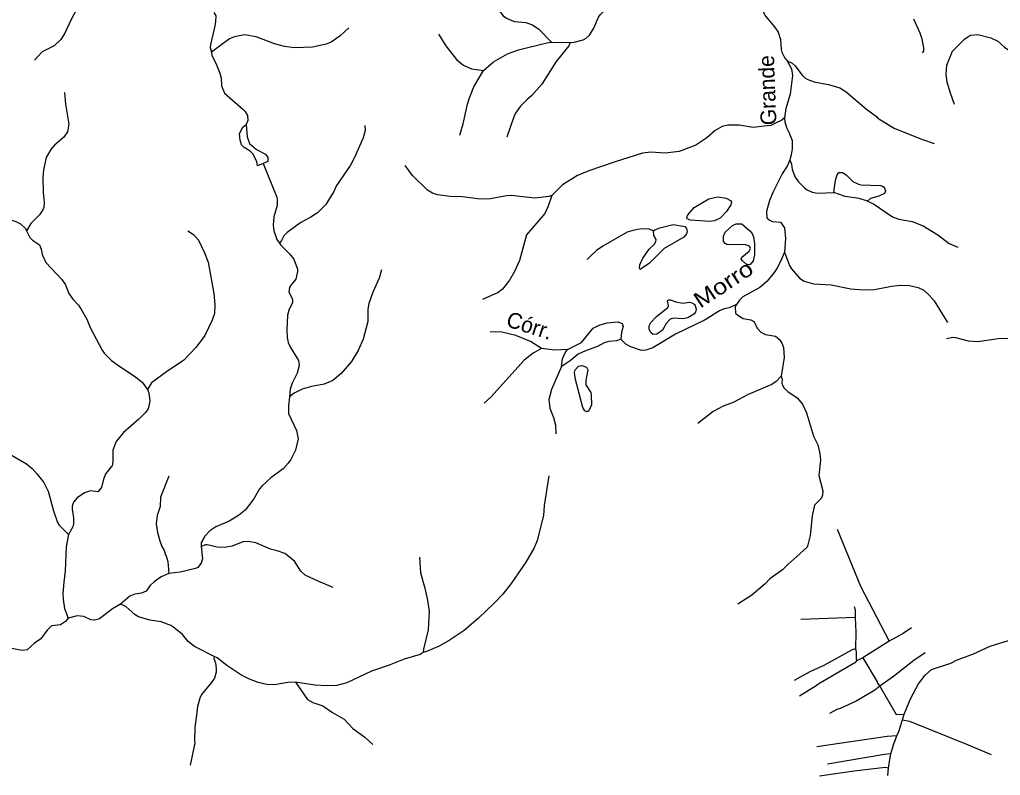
# Model space of a CAD drawing. Extents: x 346.5 to 372.4, y 7400.3 to 7428.2.
# Drawn here: x 356.096 to 361.094, y 7410.774 to 7414.626 of the extents above; entities that cross this region are included whole.
import ezdxf
from ezdxf.enums import TextEntityAlignment as Align

# ---------------------------------------------------------------- set-up
doc = ezdxf.new("R2010")
doc.units = 0
doc.header["$LTSCALE"] = 0.032
for name, color, linetype, lineweight in [('1', 7, 'Continuous', 25), ('2', 7, 'Continuous', 25), ('7', 7, 'Continuous', 25)]:
    doc.layers.add(name, color=color, linetype=linetype, lineweight=lineweight)
doc.layers.add('61', color=7, linetype='Continuous')

msp = doc.modelspace()

# ---------------------------------------------------------------- linework, layer by layer
at = {"layer": '1'}
msp.add_line((360.3537, 7411.5783), (360.0779, 7411.5678), dxfattribs=at)
for points in [[(360.262, 7412.0292), (360.3823, 7411.7384), (360.5278, 7411.4572)], [(360.3489, 7411.634), (360.3544, 7411.6172), (360.3537, 7411.5783)], [(360.3537, 7411.5783), (360.3576, 7411.5041), (360.3554, 7411.4183)], [(360.6406, 7411.5256), (360.5991, 7411.4977), (360.5278, 7411.4572), (360.3927, 7411.3731), (360.3618, 7411.3568)], [(360.3554, 7411.4183), (360.3398, 7411.414), (360.1951, 7411.3343), (360.1241, 7411.3008), (360.0429, 7411.257)], [(360.3554, 7411.4183), (360.36, 7411.4029), (360.3589, 7411.3696), (360.3618, 7411.3568)], [(360.3927, 7411.3731), (360.4668, 7411.2498), (360.4675, 7411.2439), (360.4807, 7411.2277)], [(360.7107, 7411.3981), (360.6541, 7411.3598), (360.5497, 7411.2769), (360.4807, 7411.2277)], [(360.3618, 7411.3568), (360.3533, 7411.3475), (360.1688, 7411.2411), (360.1664, 7411.2371), (360.1584, 7411.2347), (360.156, 7411.2307), (360.0699, 7411.1781)], [(360.4807, 7411.2277), (360.4549, 7411.2084), (360.3592, 7411.1526), (360.2748, 7411.1127), (360.2636, 7411.1111), (360.223, 7411.0889)], [(360.4807, 7411.2277), (360.5641, 7411.0848), (360.6036, 7411.0861)], [(360.5956, 7411.0574), (360.6318, 7411.0498), (360.9299, 7410.9302), (361.047, 7410.8793)], [(360.5668, 7410.9754), (360.517, 7410.9717), (360.1592, 7410.9191)], [(360.5359, 7410.8828), (360.5043, 7410.88), (360.2134, 7410.8314)], [(360.5245, 7410.8109), (360.5067, 7410.8143), (360.3497, 7410.7956), (360.172, 7410.7701)]]:
    msp.add_lwpolyline(points, dxfattribs=at)
at = {"layer": '2'}
for points in [[(357.2516, 7414.0922), (357.2559, 7414.0287), (357.2675, 7413.9947), (357.3039, 7413.9643), (357.3487, 7413.9397), (357.361, 7413.9232), (357.3617, 7413.9032), (357.3384, 7413.8931), (357.3092, 7413.8804), (357.3048, 7413.9011), (357.2862, 7413.9405), (357.2719, 7413.9549), (357.2404, 7413.9736), (357.2278, 7413.9877), (357.2202, 7414.0114), (357.2177, 7414.0438), (357.2328, 7414.0755)], [(360.2452, 7413.7441), (360.2537, 7413.8083), (360.2621, 7413.835), (360.2718, 7413.8459), (360.2906, 7413.8459), (360.3088, 7413.8354), (360.342, 7413.801), (360.371, 7413.7879), (360.3858, 7413.7846), (360.4815, 7413.7797), (360.4931, 7413.7775), (360.5022, 7413.7716), (360.5095, 7413.7525), (360.5038, 7413.7401), (360.4749, 7413.7265), (360.4323, 7413.7143), (360.4171, 7413.7009), (360.3745, 7413.7135), (360.3033, 7413.7248)], [(359.6537, 7413.7225), (359.6974, 7413.7154), (359.7188, 7413.7044), (359.7234, 7413.6961), (359.721, 7413.6822), (359.6982, 7413.6483), (359.666, 7413.6142), (359.6379, 7413.6011), (359.6137, 7413.5964), (359.5151, 7413.6033), (359.4981, 7413.6097), (359.4965, 7413.6175), (359.5022, 7413.6313), (359.5331, 7413.6678), (359.6084, 7413.7127)], [(359.3275, 7413.5491), (359.3337, 7413.5543), (359.3585, 7413.5651), (359.427, 7413.5823), (359.4863, 7413.5712), (359.4947, 7413.5615), (359.499, 7413.5446), (359.495, 7413.5345), (359.4812, 7413.5178), (359.3809, 7413.4597), (359.3056, 7413.3838), (359.2594, 7413.3527), (359.2546, 7413.3583), (359.2571, 7413.3768), (359.273, 7413.4103), (359.305, 7413.4554), (359.33, 7413.4795), (359.3392, 7413.4956), (359.3396, 7413.5046), (359.3276, 7413.5256)], [(359.7299, 7413.577), (359.7472, 7413.5846), (359.7769, 7413.5849), (359.8184, 7413.5491), (359.8296, 7413.5359), (359.8361, 7413.5183), (359.8421, 7413.4828), (359.8407, 7413.4263), (359.8338, 7413.3961), (359.8185, 7413.3786), (359.8078, 7413.3767), (359.7973, 7413.3804), (359.7796, 7413.3967), (359.7741, 7413.4073), (359.7776, 7413.4147), (359.8138, 7413.4458), (359.8206, 7413.4596), (359.8162, 7413.4716), (359.7955, 7413.4772), (359.7012, 7413.4802), (359.6918, 7413.4841), (359.6838, 7413.4947), (359.6832, 7413.5229), (359.6916, 7413.5433)], [(359.3442, 7413.022), (359.3247, 7413.0212), (359.3135, 7413.032), (359.304, 7413.0458), (359.3039, 7413.065), (359.3126, 7413.0822), (359.3417, 7413.1131), (359.3996, 7413.159), (359.403, 7413.1692), (359.3984, 7413.1905), (359.4012, 7413.1972), (359.4115, 7413.1984), (359.4404, 7413.1883), (359.4761, 7413.1805), (359.5095, 7413.1851), (359.5213, 7413.1829), (359.5379, 7413.1736), (359.5445, 7413.15), (359.5406, 7413.1356), (359.533, 7413.1251), (359.5015, 7413.1051), (359.4765, 7413.1003), (359.4278, 7413.1039), (359.4115, 7413.0983), (359.3908, 7413.0774), (359.372, 7413.0436)], [(358.8577, 7412.8582), (358.8629, 7412.8961), (358.8766, 7412.9277), (358.8883, 7412.9453), (358.9606, 7412.9805), (359.0187, 7413.0539), (359.0493, 7413.069), (359.091, 7413.0806), (359.1447, 7413.0863), (359.1671, 7413.0762), (359.1714, 7413.0611), (359.1636, 7413.0336), (359.1602, 7412.998), (359.1389, 7412.9887), (359.0984, 7412.985), (359.0752, 7412.9785), (359.042, 7412.9597), (358.9798, 7412.9373), (358.9429, 7412.9199), (358.9022, 7412.8861), (358.8763, 7412.8693)], [(358.9814, 7412.7875), (358.9814, 7412.7644), (359.0067, 7412.7261), (359.0096, 7412.7125), (359.0104, 7412.6623), (358.9976, 7412.6313), (358.9882, 7412.6274), (358.9774, 7412.6326), (358.9669, 7412.6497), (358.929, 7412.7916), (358.9242, 7412.8273), (358.9273, 7412.8411), (358.9445, 7412.8593), (358.9608, 7412.8635), (358.9861, 7412.8548), (358.9922, 7412.8401)]]:
    msp.add_lwpolyline(points, close=True, dxfattribs=at)
at = {"layer": '7'}
for points in [[(359.8079, 7415.1905), (359.799, 7415.162), (359.795, 7415.0983), (359.7775, 7415.0473), (359.7711, 7415.009), (359.7846, 7414.8943), (359.7942, 7414.8656), (359.8476, 7414.7715), (359.8842, 7414.6695), (359.897, 7414.644), (359.9432, 7414.5898), (359.9615, 7414.5627), (359.9743, 7414.5245), (359.9767, 7414.4735), (359.9799, 7414.4607), (359.9958, 7414.4296), (360.0086, 7414.4156)], [(356.6008, 7414.9655), (356.5562, 7414.9341), (356.5355, 7414.9078), (356.5267, 7414.8935), (356.4956, 7414.8034), (356.4829, 7414.7779), (356.4669, 7414.7524), (356.4462, 7414.7285), (356.3817, 7414.6671), (356.3586, 7414.6265), (356.3275, 7414.5564), (356.3068, 7414.5245), (356.2725, 7414.4926), (356.2119, 7414.4623), (356.1729, 7414.4201)], [(357.966, 7414.9453), (358.013, 7414.9532), (358.029, 7414.9604), (358.0616, 7414.9875), (358.0736, 7414.9939), (358.1166, 7414.9995), (358.2027, 7414.9859), (358.2601, 7414.9732), (358.3207, 7414.9516), (358.3382, 7414.9421), (358.3868, 7414.9054), (358.4027, 7414.8895), (358.4338, 7414.8465), (358.5223, 7414.6966), (358.5613, 7414.6456), (358.5773, 7414.6329), (358.6044, 7414.6209), (358.6187, 7414.6169), (358.6761, 7414.6113), (358.7104, 7414.5986), (358.743, 7414.5771), (358.8069, 7414.5119)], [(358.9026, 7414.5094), (358.9227, 7414.5104), (358.9678, 7414.5229), (358.9837, 7414.5316), (359.0012, 7414.5468), (359.0219, 7414.5819), (359.0459, 7414.6377), (359.0546, 7414.6504), (359.1168, 7414.7142), (359.1415, 7414.746), (359.1654, 7414.7819), (359.2116, 7414.8353), (359.2579, 7414.8711), (359.2802, 7414.8807), (359.3257, 7414.8812)], [(357.086, 7414.6629), (357.0965, 7414.6458), (357.0949, 7414.6153), (357.0902, 7414.5851), (357.0686, 7414.499), (357.0678, 7414.4846), (357.0737, 7414.4603)], [(360.6509, 7414.6297), (360.6844, 7414.5588), (360.6939, 7414.5277), (360.7019, 7414.483), (360.7019, 7414.4647), (360.6963, 7414.4575)], [(357.7747, 7414.5843), (357.7293, 7414.5436), (357.6839, 7414.5109), (357.6592, 7414.5006), (357.5891, 7414.4862), (357.4966, 7414.483), (357.4456, 7414.4886), (357.3946, 7414.5022), (357.3022, 7414.538), (357.2432, 7414.5484), (357.1922, 7414.538), (357.1667, 7414.5285), (357.0737, 7414.4603)], [(358.2314, 7414.5524), (358.2688, 7414.4926), (358.323, 7414.4233), (358.3445, 7414.4033), (358.3581, 7414.393), (358.3988, 7414.3754), (358.4606, 7414.366)], [(358.4606, 7414.366), (358.5119, 7414.4105), (358.5821, 7414.4512), (358.6394, 7414.4719), (358.7829, 7414.5085), (358.8069, 7414.5119), (358.9026, 7414.5094)], [(358.9026, 7414.5094), (358.8949, 7414.4927), (358.8311, 7414.4129), (358.7574, 7414.2966), (358.7072, 7414.2384), (358.6809, 7414.2169), (358.649, 7414.1842), (358.6275, 7414.1547), (358.6171, 7414.1356), (358.5789, 7414.0264)], [(360.8605, 7414.1938), (360.8398, 7414.2503), (360.8231, 7414.3077), (360.8183, 7414.346), (360.8215, 7414.3938), (360.851, 7414.4655), (360.9115, 7414.5269), (360.9283, 7414.5388), (360.9442, 7414.5468), (360.9793, 7414.55), (361.0462, 7414.534), (361.0813, 7414.5165), (361.1155, 7414.4854), (361.1331, 7414.4735), (361.1626, 7414.4607), (361.1913, 7414.4551), (361.2199, 7414.4551), (361.2391, 7414.4615), (361.2917, 7414.4894), (361.318, 7414.5053), (361.339, 7414.5146), (361.3631, 7414.5436)], [(357.0737, 7414.4603), (357.0758, 7414.4438), (357.0965, 7414.4034), (357.1172, 7414.3523), (357.1228, 7414.3268), (357.1244, 7414.2886), (357.1404, 7414.2503), (357.2336, 7414.169), (357.2456, 7414.1571), (357.2575, 7414.138), (357.2591, 7414.1125), (357.2516, 7414.0922)], [(360.0086, 7414.4156), (360.0293, 7414.3755), (360.0349, 7414.3404), (360.0229, 7414.2456), (360.0014, 7414.1722), (359.994, 7414.1248)], [(360.0086, 7414.4156), (360.0336, 7414.4043), (360.0492, 7414.3905), (360.0819, 7414.3444), (360.0986, 7414.3292), (360.1138, 7414.3205), (360.1457, 7414.3085), (360.219, 7414.2958), (360.2764, 7414.2782), (360.3082, 7414.2575), (360.4126, 7414.169), (360.4628, 7414.1316), (360.4692, 7414.1236), (360.5051, 7414.1013), (360.5537, 7414.0734), (360.5824, 7414.0606), (360.6971, 7414.0144), (360.7569, 7413.9937)], [(358.339, 7414.0376), (358.3573, 7414.0941), (358.3788, 7414.1946), (358.3892, 7414.228), (358.4115, 7414.2838), (358.4606, 7414.366)], [(356.3251, 7414.2543), (356.3299, 7414.1946), (356.3466, 7414.0925), (356.341, 7414.0543), (356.3219, 7414.0272), (356.2749, 7413.9857), (356.2558, 7413.9642), (356.2326, 7413.9236), (356.2183, 7413.8598), (356.2151, 7413.8216), (356.2167, 7413.7451), (356.2215, 7413.6941), (356.2199, 7413.6686), (356.2151, 7413.6558), (356.1976, 7413.6311), (356.1537, 7413.5865), (356.1321, 7413.5493)], [(359.994, 7414.1248), (359.9799, 7414.1139), (359.9483, 7414.0974), (359.9249, 7414.087), (359.9066, 7414.0838), (359.8349, 7414.0766), (359.7631, 7414.0885), (359.7057, 7414.0885), (359.6771, 7414.0806), (359.6412, 7414.0607), (359.5981, 7414.024), (359.5416, 7413.9865), (359.4571, 7413.9539), (359.3854, 7413.9459), (359.3136, 7413.9499), (359.2706, 7413.9459), (359.1256, 7413.8997), (358.9965, 7413.8558), (358.9391, 7413.8319), (358.8634, 7413.7841), (358.8094, 7413.73)], [(359.994, 7414.1248), (359.9961, 7414.1055), (360.0046, 7414.0758), (360.0165, 7414.0527), (360.0325, 7414.0097), (360.0325, 7413.9666), (360.0285, 7413.9363), (360.0212, 7413.9119)], [(357.8552, 7414.087), (357.8568, 7414.0607), (357.8472, 7414.024), (357.8026, 7413.9236), (357.7819, 7413.8837), (357.7118, 7413.7809), (357.6974, 7413.7499), (357.6576, 7413.6829), (357.6146, 7413.6407), (357.5811, 7413.6183), (357.5301, 7413.5912), (357.4592, 7413.5402), (357.4432, 7413.5243), (357.4316, 7413.4998), (357.421, 7413.4864)], [(360.0212, 7413.9119), (360.0102, 7413.8829), (359.9831, 7413.8391), (359.9368, 7413.7483), (359.9177, 7413.7036), (359.9018, 7413.6478), (359.905, 7413.616), (359.9161, 7413.6048), (359.9313, 7413.5976), (359.9735, 7413.5928), (359.9942, 7413.5642), (359.999, 7413.5108), (359.9942, 7413.4403)], [(360.0212, 7413.9119), (360.0302, 7413.8885), (360.0341, 7413.8614), (360.0484, 7413.8232), (360.0652, 7413.7985), (360.0962, 7413.7682), (360.1106, 7413.7578), (360.1361, 7413.7459), (360.1616, 7413.7419), (360.2452, 7413.7441)], [(357.3384, 7413.8931), (357.4065, 7413.7212), (357.4097, 7413.7068), (357.4097, 7413.6781), (357.3922, 7413.6208), (357.3882, 7413.5777), (357.3922, 7413.549), (357.4018, 7413.5203), (357.4073, 7413.5052), (357.421, 7413.4864)], [(358.8094, 7413.73), (358.7929, 7413.7252), (358.7223, 7413.7164), (358.6458, 7413.7243), (358.6044, 7413.7291), (358.5789, 7413.7283), (358.4944, 7413.7132), (358.4434, 7413.71), (358.3541, 7413.7219), (358.2904, 7413.7251), (358.2266, 7413.7331), (358.2011, 7413.7411), (358.1748, 7413.7562), (358.0991, 7413.8311), (358.0616, 7413.8822)], [(355.7154, 7413.8383), (355.7481, 7413.7849), (355.8135, 7413.6909), (355.8469, 7413.6606), (355.8979, 7413.6375), (355.9617, 7413.616), (355.9872, 7413.6104), (356.0494, 7413.6056), (356.078, 7413.5976), (356.1011, 7413.5857), (356.1258, 7413.561), (356.1321, 7413.5493)], [(358.8094, 7413.73), (358.79, 7413.6749), (358.7725, 7413.6383), (358.6793, 7413.5283), (358.6434, 7413.3976), (358.6179, 7413.3418), (358.5932, 7413.2972), (358.5565, 7413.2526), (358.5358, 7413.235), (358.4553, 7413.1992)], [(360.4171, 7413.7009), (360.4477, 7413.6877), (360.5441, 7413.6215), (360.5776, 7413.6096), (360.6445, 7413.5968), (360.7003, 7413.5745), (360.7752, 7413.5283), (360.8342, 7413.4853), (360.878, 7413.4661)], [(359.3275, 7413.5491), (359.3041, 7413.5586), (359.2658, 7413.5594), (359.2276, 7413.553), (359.1925, 7413.5426), (359.0682, 7413.4709), (359.0363, 7413.4486), (359.0085, 7413.4231), (358.9895, 7413.4035)], [(356.1321, 7413.5493), (356.1482, 7413.5155), (356.1625, 7413.502), (356.1984, 7413.4781), (356.2071, 7413.4566), (356.2119, 7413.4295), (356.2294, 7413.3888), (356.3115, 7413.302), (356.3299, 7413.2733), (356.3474, 7413.2302), (356.3673, 7413.2016), (356.396, 7413.1713), (356.4143, 7413.1426), (356.4398, 7413.0995), (356.4558, 7413.0565), (356.5164, 7412.941), (356.5275, 7412.9258), (356.565, 7412.8891), (356.5945, 7412.866), (356.6885, 7412.8031), (356.7204, 7412.7784), (356.7484, 7412.7398)], [(356.9539, 7413.549), (356.9834, 7413.5307), (357.0073, 7413.5012), (357.0392, 7413.4375), (357.0567, 7413.3896), (357.0854, 7413.2302), (357.0917, 7413.1729), (357.0902, 7413.1274), (357.0782, 7413.0932), (357.0407, 7413.0167), (356.9953, 7412.9561), (356.934, 7412.8907), (356.8447, 7412.831), (356.7682, 7412.7744), (356.7484, 7412.7398)], [(357.421, 7413.4864), (357.4272, 7413.4761), (357.4711, 7413.4327), (357.4934, 7413.4056), (357.5117, 7413.3546), (357.5117, 7413.3418), (357.5046, 7413.3028), (357.4807, 7413.2733), (357.4719, 7413.2605), (357.4679, 7413.2366), (357.487, 7413.2008), (357.487, 7413.184), (357.4687, 7413.1458), (357.4615, 7413.1203), (357.4575, 7413.0438), (357.4599, 7413.0055), (357.4655, 7412.98), (357.4767, 7412.9545), (357.5173, 7412.8876), (357.5205, 7412.8621), (357.5109, 7412.8238), (357.4862, 7412.7728), (357.4759, 7412.7417), (357.4724, 7412.7036)], [(359.9942, 7413.4403), (359.9743, 7413.3928), (359.9544, 7413.3578), (359.9408, 7413.3362), (359.9058, 7413.2932), (359.8691, 7413.2605), (359.7822, 7413.2135), (359.7645, 7413.1967), (359.749, 7413.1737)], [(359.9942, 7413.4403), (360.0189, 7413.3721), (360.0293, 7413.3562), (360.0707, 7413.3075), (360.0946, 7413.2924), (360.1425, 7413.2796), (360.2317, 7413.2741), (360.3321, 7413.2533), (360.3943, 7413.2494), (360.4533, 7413.251), (360.5394, 7413.2669), (360.584, 7413.2717), (360.6318, 7413.2709), (360.6748, 7413.2597), (360.7035, 7413.2462), (360.7314, 7413.2223), (360.7577, 7413.192), (360.8255, 7413.0828)], [(357.9405, 7413.3506), (357.9285, 7413.3083), (357.8959, 7413.2366), (357.8759, 7413.1792), (357.8712, 7413.1506), (357.8704, 7413.0868), (357.848, 7412.9975), (357.8217, 7412.9402), (357.7883, 7412.8828), (357.7357, 7412.8214), (357.6927, 7412.7863), (357.648, 7412.768), (357.5843, 7412.7561), (357.5365, 7412.7417), (357.496, 7412.7222), (357.4724, 7412.7036)], [(359.749, 7413.1737), (359.7121, 7413.1561), (359.6866, 7413.1513), (359.6635, 7413.141), (359.5902, 7413.0955), (359.438, 7413.0222), (359.3232, 7412.9529), (359.2881, 7412.9417), (359.265, 7412.9401), (359.2116, 7412.9577), (359.1853, 7412.972), (359.1602, 7412.998)], [(359.749, 7413.1737), (359.7435, 7413.1627), (359.7448, 7413.129), (359.7559, 7413.1195), (359.7838, 7413.1027), (359.8221, 7413.0955), (359.8388, 7413.0876), (359.8571, 7413.0517), (359.8731, 7413.0326), (359.897, 7413.0214), (359.948, 7413.0119), (359.9711, 7412.9935), (359.9815, 7412.9776), (359.9886, 7412.9545), (359.9926, 7412.9035), (359.9768, 7412.8082)], [(358.7556, 7412.9504), (358.7, 7412.9848), (358.6258, 7413.0166), (358.5534, 7413.0334), (358.4936, 7413.0342)], [(361.3629, 7413.0395), (361.345, 7413.0095), (361.3156, 7412.9832), (361.2837, 7412.9712), (361.2678, 7412.9688), (361.2247, 7412.9744), (361.1673, 7412.9935), (361.1387, 7412.9991), (361.0956, 7413.0007), (360.9793, 7412.9832), (360.9314, 7412.9864), (360.8677, 7413.0047), (360.8518, 7413.0055), (360.8191, 7412.9983)], [(358.7556, 7412.9504), (358.7128, 7412.9258), (358.6681, 7412.8907), (358.4984, 7412.7007), (358.4633, 7412.6716)], [(358.8883, 7412.9453), (358.8243, 7412.9417), (358.7556, 7412.9504)], [(358.8577, 7412.8582), (358.8076, 7412.7409), (358.794, 7412.6899), (358.7988, 7412.6453), (358.8171, 7412.5975), (358.8275, 7412.5592), (358.8291, 7412.5154)], [(359.9768, 7412.8082), (359.952, 7412.7816), (359.9305, 7412.7664), (359.8093, 7412.7154), (359.7328, 7412.674), (359.6818, 7412.6556), (359.6308, 7412.6277), (359.5527, 7412.568)], [(359.9768, 7412.8082), (359.9823, 7412.7917), (359.9805, 7412.7714), (359.9847, 7412.764), (359.991, 7412.7489), (360.0117, 7412.7298), (360.058, 7412.6987), (360.0859, 7412.666), (360.1066, 7412.6214), (360.1425, 7412.5034), (360.1648, 7412.4588), (360.1751, 7412.4142), (360.1783, 7412.3807), (360.1696, 7412.3026), (360.1895, 7412.2245), (360.1871, 7412.2022), (360.1807, 7412.1854), (360.1472, 7412.1504), (360.1353, 7412.097), (360.1257, 7411.9966), (360.1138, 7411.9488), (360.109, 7411.9368), (360.0564, 7411.889), (360.0118, 7411.8483), (359.9839, 7411.8212), (359.9201, 7411.7758), (359.8954, 7411.7503), (359.8285, 7411.6921), (359.7559, 7411.6459)], [(356.7484, 7412.7398), (356.7546, 7412.724), (356.7602, 7412.6804), (356.7523, 7412.6429), (356.7371, 7412.6222), (356.7036, 7412.5887), (356.6263, 7412.5218), (356.5881, 7412.4747), (356.5721, 7412.4317), (356.5721, 7412.3743), (356.5689, 7412.3496), (356.5634, 7412.3472), (356.5363, 7412.3122), (356.5243, 7412.2835), (356.514, 7412.2412), (356.4956, 7412.2189), (356.4574, 7412.2245), (356.4271, 7412.2141), (356.3896, 7412.1886), (356.3705, 7412.1671), (356.3649, 7412.1464), (356.3649, 7412.1305), (356.3713, 7412.0858), (356.3713, 7412.0556), (356.3681, 7412.0412), (356.3449, 7412.0009)], [(357.4724, 7412.7036), (357.4671, 7412.6596), (357.4663, 7412.619), (357.507, 7412.5321), (357.5157, 7412.4891), (357.5022, 7412.4317), (357.4791, 7412.3839), (357.4647, 7412.3656), (357.44, 7412.3369), (357.3771, 7412.2906), (357.3308, 7412.2484), (357.3181, 7412.2341), (357.2918, 7412.1862), (357.2798, 7412.1703), (357.2456, 7412.1257), (357.2113, 7412.0986), (357.1651, 7412.0699), (357.0965, 7412.0412), (357.0654, 7412.0197), (357.0407, 7411.9934), (357.028, 7411.9727), (357.0248, 7411.9615), (357.0219, 7411.9617), (357.0212, 7411.9396)], [(355.8453, 7412.5673), (355.8748, 7412.5464), (355.9649, 7412.4923), (356.0191, 7412.4293), (356.0462, 7412.4102), (356.1322, 7412.3616), (356.1601, 7412.3385), (356.1864, 7412.309), (356.2191, 7412.2659), (356.2422, 7412.2229), (356.2693, 7412.1225), (356.2892, 7412.0635), (356.2988, 7412.0484), (356.3449, 7412.0009)], [(356.8575, 7412.2986), (356.8144, 7412.1926), (356.812, 7412.1448), (356.7977, 7412.0986), (356.7929, 7412.0556), (356.7985, 7412.0125), (356.8104, 7411.9695), (356.8208, 7411.9408), (356.8327, 7411.92), (356.8399, 7411.8961), (356.8415, 7411.8985), (356.8511, 7411.8643), (356.8576, 7411.8023)], [(358.794, 7412.3002), (358.7701, 7412.1496), (358.7669, 7412.0986), (358.7343, 7411.9711), (358.7191, 7411.9328), (358.6761, 7411.8603), (358.6012, 7411.7519), (358.5589, 7411.6977), (358.5151, 7411.6507), (358.4354, 7411.5758), (358.3621, 7411.5128), (358.2904, 7411.465), (358.2346, 7411.4323), (358.1697, 7411.4043), (358.1532, 7411.4002)], [(356.3449, 7412.0009), (356.3331, 7411.9392), (356.3283, 7411.8165), (356.3211, 7411.7591), (356.3171, 7411.7001), (356.3187, 7411.6698), (356.3251, 7411.6236), (356.3442, 7411.5746)], [(357.695, 7411.732), (357.6209, 7411.7615), (357.5516, 7411.7949), (357.5301, 7411.8141), (357.4966, 7411.8651), (357.4472, 7411.9041), (357.4089, 7411.9185), (357.3747, 7411.9264), (357.3006, 7411.9583), (357.2607, 7411.9663), (357.2336, 7411.9639), (357.1794, 7411.9416), (357.1412, 7411.9352), (357.1029, 7411.9376), (357.0519, 7411.9487), (357.0439, 7411.9487), (357.0212, 7411.9396)], [(357.0212, 7411.9396), (357.0288, 7411.877), (357.0208, 7411.8547), (357.0041, 7411.8332), (356.9929, 7411.8276), (356.9148, 7411.8101), (356.8576, 7411.8023)], [(358.1342, 7411.8858), (358.1389, 7411.8069), (358.162, 7411.7272), (358.1756, 7411.6666), (358.1836, 7411.6093), (358.1788, 7411.5152), (358.154, 7411.4174), (358.1532, 7411.4002)], [(356.8576, 7411.8023), (356.8184, 7411.7854), (356.7817, 7411.7607), (356.7618, 7411.7423), (356.7411, 7411.7121), (356.718, 7411.7025), (356.6837, 7411.6977), (356.6582, 7411.6865), (356.6107, 7411.6467)], [(356.6107, 7411.6467), (356.569, 7411.6228), (356.5036, 7411.5718), (356.4781, 7411.5646), (356.4598, 7411.567), (356.4239, 7411.5829), (356.3889, 7411.5869), (356.3442, 7411.5746)], [(357.0884, 7411.379), (356.9874, 7411.4299), (356.9555, 7411.4562), (356.9268, 7411.4913), (356.883, 7411.5272), (356.867, 7411.5383), (356.8176, 7411.5559), (356.7602, 7411.5646), (356.7029, 7411.5814), (356.6853, 7411.5925), (356.6375, 7411.6348), (356.6107, 7411.6467)], [(356.3442, 7411.5746), (356.3299, 7411.5582), (356.3044, 7411.5415), (356.2582, 7411.5367), (356.2366, 7411.5144), (356.2039, 7411.469), (356.1721, 7411.4475), (356.1346, 7411.414), (356.1099, 7411.41), (356.0382, 7411.4243), (356.0076, 7411.4178)], [(360.5202, 7410.7725), (360.5245, 7410.8109), (360.5314, 7410.8554), (360.5359, 7410.8828), (360.5489, 7410.9287), (360.5668, 7410.9754), (360.5776, 7410.9972), (360.5956, 7411.0574), (360.6036, 7411.0861), (360.6374, 7411.1678), (360.6764, 7411.2411), (360.7115, 7411.2849), (360.7434, 7411.3128), (360.8422, 7411.3462), (360.8709, 7411.3606), (360.957, 7411.3933), (361.043, 7411.4315), (361.1354, 7411.4609)], [(357.0884, 7411.379), (357.0869, 7411.369), (357.0949, 7411.3479), (357.0989, 7411.316), (357.0981, 7411.3), (357.0894, 7411.2698), (357.0734, 7411.2451), (357.0232, 7411.1861), (357.0144, 7411.1678), (357.0025, 7411.1247), (356.9889, 7411.0147), (356.9873, 7410.9526), (356.9897, 7410.9326), (356.9873, 7410.9318), (356.9658, 7410.8259)], [(357.5023, 7411.2488), (357.4631, 7411.2474), (357.3946, 7411.2347), (357.3563, 7411.2371), (357.3117, 7411.2466), (357.2671, 7411.2634), (357.2241, 7411.2865), (357.1523, 7411.3343), (357.1037, 7411.3726), (357.0884, 7411.379)], [(358.1532, 7411.4002), (358.1374, 7411.3905), (358.0561, 7411.3654), (357.9796, 7411.3351), (357.8903, 7411.3048), (357.7644, 7411.245), (357.7134, 7411.2323), (357.664, 7411.2299), (357.6002, 7411.2339), (357.5023, 7411.2488)], [(357.5023, 7411.2488), (357.5643, 7411.1598), (357.5907, 7411.1446), (357.6408, 7411.1279), (357.6903, 7411.0936), (357.75, 7411.0594), (357.7947, 7411.0131), (357.8552, 7410.9685), (357.8959, 7410.9319)]]:
    msp.add_lwpolyline(points, dxfattribs=at)

# ---------------------------------------------------------------- texts
at = {"layer": '61'}
for s, rotation, p in [('Grande', 92.103, (359.9469, 7414.2675)), ('Córr.', 342.289, (358.6837, 7413.0284))]:
    msp.add_text(s, height=0.08, rotation=rotation, dxfattribs=at).set_placement(p, align=Align.CENTER)
at = {"layer": '61', "width": 1.2}
msp.add_text('Morro', height=0.08, rotation=33.607, dxfattribs=at).set_placement((359.7046, 7413.2445), align=Align.CENTER)

doc.saveas('drawing.dxf')
